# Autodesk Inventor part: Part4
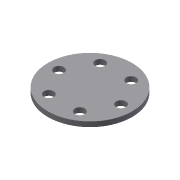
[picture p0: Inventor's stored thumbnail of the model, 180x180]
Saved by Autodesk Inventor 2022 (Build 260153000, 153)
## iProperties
Created: 2008-05
Part Number: Part4
Document SubType Name: Modeling
Designer: CADCIM
Density: 1 g/cm^3
Material: Generic
Appearance: Default
Author: CADCIM
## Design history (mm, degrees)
sketch "Sketch1"
  geometry: C1 r 17 at (0, 0)
  constraints: 1 centre point, 1 other
  dimensions: "d12" = 34 diameter of C1
extrude "Extrusion1" new body sketch "Sketch1" distance "d0" = 2; taper "d1" = 0 deg
sketch "Sketch2"
  geometry: 1 further point
hole "Hole1" sketch "Sketch2" at (5.9, 10.769) diameter "d2" = 4; stored, may be unused: countersink angle "d6" = 90 deg, drill point angle "d8" = 118 deg; dims "d3" = 6, "d4" = 4, "d5" = 2, "d7" = 8
pattern_circular "Circular Pattern1" dims angle "d10" = 360 deg
body "Solid1"
